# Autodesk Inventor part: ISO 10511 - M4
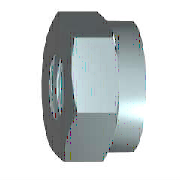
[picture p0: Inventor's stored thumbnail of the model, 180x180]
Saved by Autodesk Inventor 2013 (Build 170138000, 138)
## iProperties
IsCustomPart: 0
Created: 2012-02
Part Number: ISO 10511 - M4
Material: Stahl, weich
Description: Sechskantmutter
Document SubType Name: Modeling
Standard: ISO 10511
Designer: rYan
Standard Revision: 1998
Standards Organization: DIN
Language: de-DE
Size Designation: M4
Categories: <MemberInstance><Categories><Category DisplayName="Verbindungselemente" InternalName="e4da775c-781d-43d5-af7c-5136215cf5a6" Mnemonic="FSTN"><Category DisplayNam
Density: 7.86 g/cm^3
Mass: 0.920066 g
Surface Area: 2.04052 cm^2
Volume: 0.117057 cm^3
Author: rYan
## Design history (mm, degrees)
sketch "Skizze1"
  geometry: L1 (2.021, -3.5)-(-2.021, -3.5); L2 (-2.021, -3.5)-(-4.041, 0); L3 (-4.041, 0)-(-2.021, 3.5); L4 (-2.021, 3.5)-(2.021, 3.5); L5 (2.021, 3.5)-(4.041, 0); L6 (4.041, 0)-(2.021, -3.5); 2 further points
  constraints: 12 end point, 1 coincident, 1 horizontal, 11 other
  dimensions: "d0" = 8.0829 distance of L5.end L2.end (= 1.1547 x SW)
extrude "Körper" new body sketch "Skizze1" distance "d1" = 1.95 (= KOH1); taper "d2" = 0 deg
sketch "Skizze2"
  geometry: C1 r 2.95 at (0, 0); 1 further point
  constraints: 1 centre point, 1 coincident
  dimensions: "d7" = 5.9 diameter of C1 (= SD2)
extrude "Ring" join sketch "Skizze2" distance "d8" = 3.05 (= KOH - KOH1); taper "d9" = 0 deg
sketch "Skizze3"
  geometry: L1 (0, 2.021)-(0, 4.041) reference; L2 (0, 4.041)-(1.95, 4.041) reference; L3 (1.95, 2.021)-(1.95, 4.041) reference; L4 (-0.39, 0)-(2.34, 0) reference; L5 (0, 2.95)-(0.63, 4.041); L6 (1.32, 4.041)-(1.95, 2.95)
  constraints: 4 end point, 4 point on line
  dimensions: "d3" = 30 deg angle of L5 L1 (= ANG1); "d4" = 30 deg angle of L3 L6 (= ANG2); "d5" = 5.9 diameter of L5.start L4 (= SW0); "d6" = 5.9 diameter of L6.end L4 (= SW01)
revolve "Fase1" sketch "Skizze3" stored, may be unused: angle "d26" = 90 deg
sketch "Skizze4"
  geometry: L1 (0, -5.658)-(0, 5.658) reference; L2 (-4.9, 0)-(4.9, 0) reference; 1 further point
  constraints: 2 midpoint
hole "Gewinde" sketch "Skizze4" at (0, 0) diameter "d30" = 3.242; stored, may be unused: countersink angle "d34" = 82 deg, drill point angle "d36" = 118 deg; dims "d31" = 6, "d32" = 4, "d33" = 2, "d35" = 8
workaxis "Work Axis1"
workplane "Work Plane1"
body "Solid1"
chamfer "Fase2" distance "d10" = 0.37889 (= -0.5 x GD1 + 0.5 x NND); stored, may be unused: angle "d11" = 30 deg, second distance "d46" = 0.37889 (= -0.5 x GD1 + 0.5 x NND)
chamfer "Fase3" distance "d12" = 0.37889 (= -0.5 x GD1 + 0.5 x NND); stored, may be unused: angle "d13" = 30 deg, second distance "d47" = 0.37889 (= -0.5 x GD1 + 0.5 x NND)
other parameters: "ANG1" = 30 deg [user parameter; used in 1 equation term], "ANG2" = 30 deg [user parameter; used in 1 equation term], "NND" = 4 [user parameter; used in 4 equation terms], "KOH1" = 1.95 [user parameter; used in 2 equation terms], "KOH" = 5 [user parameter; used in 1 equation term], "SW" = 7 [user parameter; used in 2 equation terms], "SW0" = 5.9 [user parameter; used in 3 equation terms], "SW01" = 5.9 (= SW0) [user parameter; used in 1 equation term], "SD2" = 5.9 (= SW0) [user parameter; used in 1 equation term], "GD1" = 3.24223 (computed from THREADDIA, PTC, TOA) [user parameter; used in 4 equation terms], "d14" = 0, "d15" = 0, "d45" = 0, "d48" = 0, "GUL" = 0.37889 (= 0.541266 x PTC) [user parameter], "TPU" = 14.28571 (computed from PTC) [user parameter], "THREADDIA" = 4 [user parameter; used in 1 equation term], "TOA" = 30 deg [user parameter; used in 1 equation term], "PTC" = 0.7 [user parameter; used in 4 equation terms], "E0" = 8.085 (= 1.155 x SW) [user parameter], "GAL" = 0.37889 (= 0.541266 x PTC) [user parameter]
